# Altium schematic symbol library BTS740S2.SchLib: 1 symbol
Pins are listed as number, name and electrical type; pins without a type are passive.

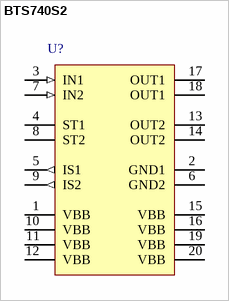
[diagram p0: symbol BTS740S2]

## BTS740S2
designator U?
Smart High-Side Power Switch, 2 Channels, 3.9 A Load Current, -40 to 150 degC, PG-DSO-20-31, Reel, Green; Manufacturer: Infineon; PartNumber: BTS740S2; Channels: 2; Green: TRUE; Group: Automotive Qualified; Load Current (typ): 3.9 A; Ptot (max): 3.8 W; Recommended Operating Voltage Max.: 34 V; Recommended Operating Voltage Min.: 5 V; RON @ 25degreesC: 30 mOhm; RON(max) @ 150degreesC: 60 mOhm; toff (max): 200 us; ton (max): 150 us
footprint INF-PG-DSO-20-31_N (SOP, 20-Leads, Body 12.7x7.5mm, Pitch 1.27mm, IPC High Density)
footprint INF-PG-DSO-20-31_L (SOP, 20-Leads, Body 12.7x7.5mm, Pitch 1.27mm, IPC High Density)
footprint INF-PG-DSO-20-31_M (SOP, 20-Leads, Body 12.7x7.5mm, Pitch 1.27mm, IPC Low Density)
pins: 1 VBB (power) "Positive power supply voltage. Design the wiring for the simultaneous max. short circuit currents from channel 1 to 2 and also for low thermal resistance", 2 GND1 (power) "Ground 1 of chip 1 (channel 1)", 3 IN1 (in) "Input 1,2, activates channel 1,2 in case of logic high signal", 4 ST1 (oc) "Diagnostic feedback 1,2 of channel 1,2, open drain, invers to input level", 5 IS1 (out) "Sense current output 1,2; proportional to the load current, zero in the case of current limitation of the load current", 6 GND2 (power) "Ground 2 of chip 2 (channel 2)", 7 IN2 (in) "Input 1,2, activates channel 1,2 in case of logic high signal", 8 ST2 (oc) "Diagnostic feedback 1,2 of channel 1,2, open drain, invers to input level", 9 IS2 (out) "Sense current output 1,2; proportional to the load current, zero in the case of current limitation of the load current", 10 VBB (power) "Positive power supply voltage. Design the wiring for the simultaneous max. short circuit currents from channel 1 to 2 and also for low thermal resistance", 11 VBB (power) "Positive power supply voltage. Design the wiring for the simultaneous max. short circuit currents from channel 1 to 2 and also for low thermal resistance", 12 VBB (power) "Positive power supply voltage. Design the wiring for the simultaneous max. short circuit currents from channel 1 to 2 and also for low thermal resistance", 13 OUT2 (power) "Output 1,2, protected high-side power output of channel 1,2. Both pins of each output have to be connected in parallel for operation according ths spec (e.g. kilis). Design the wiring for the max. short circuit current", 14 OUT2 (power) "Output 1,2, protected high-side power output of channel 1,2. Both pins of each output have to be connected in parallel for operation according ths spec (e.g. kilis). Design the wiring for the max. short circuit current", 15 VBB (power) "Positive power supply voltage. Design the wiring for the simultaneous max. short circuit currents from channel 1 to 2 and also for low thermal resistance", 16 VBB (power) "Positive power supply voltage. Design the wiring for the simultaneous max. short circuit currents from channel 1 to 2 and also for low thermal resistance", 17 OUT1 (power) "Output 1,2, protected high-side power output of channel 1,2. Both pins of each output have to be connected in parallel for operation according ths spec (e.g. kilis). Design the wiring for the max. short circuit current", 18 OUT1 (power) "Output 1,2, protected high-side power output of channel 1,2. Both pins of each output have to be connected in parallel for operation according ths spec (e.g. kilis). Design the wiring for the max. short circuit current", 19 VBB (power) "Positive power supply voltage. Design the wiring for the simultaneous max. short circuit currents from channel 1 to 2 and also for low thermal resistance", 20 VBB (power) "Positive power supply voltage. Design the wiring for the simultaneous max. short circuit currents from channel 1 to 2 and also for low thermal resistance"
